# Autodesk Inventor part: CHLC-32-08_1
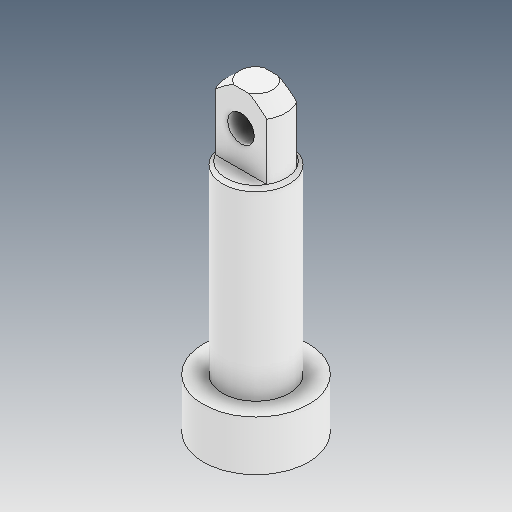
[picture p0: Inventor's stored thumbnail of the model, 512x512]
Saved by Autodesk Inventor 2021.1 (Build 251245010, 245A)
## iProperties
Created: 2021-05
Part Number: CHLC-32-08_1
Material: Ogólny
Document SubType Name: Modeling
Designer: user
Density: 1 g/cm^3
Appearance: Domyślna
Author: user
Revision Number: ÈÎºÎ
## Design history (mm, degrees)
feature "ÊäÈë1"
node "Bryła1"
